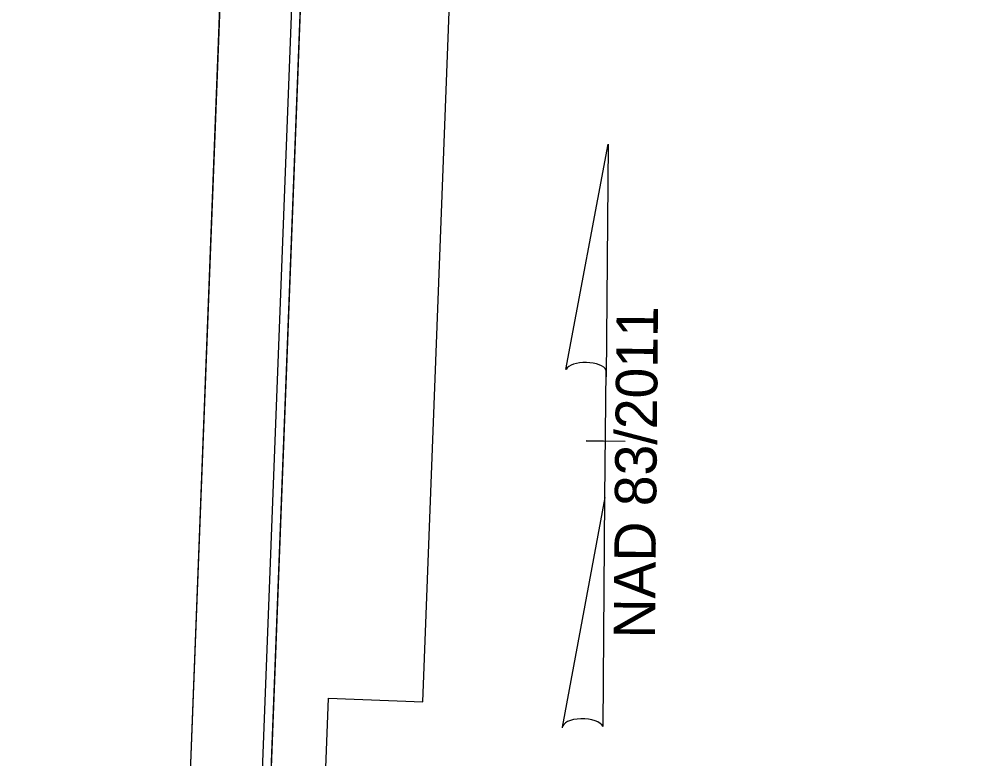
# Model space of a CAD drawing. Extents: x 2097083 to 2098242, y 681809 to 688195.
# Drawn here: x 2097083.2 to 2097350.7, y 687759.7 to 687966 of the extents above; entities that cross this region are included whole.
import ezdxf

# ---------------------------------------------------------------- set-up
doc = ezdxf.new("R2010")
doc.units = 0
for name, color, linetype in [('Prop North Arrow NAD83 for Plan Sheets CELL', 7, 'Continuous'), ('Scratch_Level_6', 7, 'Continuous'), ('Sheet Cutting Line CELL', 7, 'Continuous'), ('Sheet Plan CELL', 7, 'Continuous'), ('Sheet Plot Border Inside CELL', 7, 'Continuous'), ('Sheet Plot Border Outside CELL', 7, 'Continuous')]:
    doc.layers.add(name, color=color, linetype=linetype)

msp = doc.modelspace()

# ---------------------------------------------------------------- linework, layer by layer
at = {"layer": 'Prop North Arrow NAD83 for Plan Sheets CELL'}
for p, q in [((2097235.67, 687868.29), (2097247.39, 687931.13)), ((2097247.46, 687931.13), (2097246.86, 687866.22)), ((2097246.54, 687832.54), (2097246.87, 687868.12)), ((2097246.86, 687866.22), (2097246.87, 687868.05)), ((2097246.08, 687848.3), (2097241.26, 687848.34)), ((2097241.33, 687848.34), (2097252.19, 687848.24)), ((2097246.54, 687832.54), (2097234.61, 687768.48)), ((2097246.02, 687768.64), (2097246.54, 687832.54))]:
    msp.add_line(p, q, dxfattribs=at)
for centre, start_param, end_param in [((2097241.28, 687867.57), 0.216388, 2.908219), ((2097240.36, 687768.2), 0.201328, 3.141593)]:
    msp.add_ellipse(centre, major_axis=(5.74, -0.09), ratio=0.461098, start_param=start_param, end_param=end_param, dxfattribs=at)
at = {"layer": 'Scratch_Level_6'}
msp.add_lwpolyline([(2098163.94, 686705.88), (2097129.59, 686735.95), (2097169.5, 687776.57), (2097195.74, 687775.56), (2097203.4, 687975.46), (2097338.1, 687970.31), (2097342.47, 688084.23), (2098215.52, 688050.75)], close=True, dxfattribs=at)
at = {"layer": 'Sheet Cutting Line CELL'}
msp.add_line((2097147.77, 688194.8), (2097083.25, 686512.54), dxfattribs=at)
at = {"layer": 'Sheet Plan CELL'}
for points in [[(2097169.59, 688176.98), (2097112.1, 686678.04), (2098161.33, 686637.81), (2098218.82, 688136.72)], [(2098161.33, 686637.81), (2097112.13, 686678.02), (2097161.91, 687977.05), (2097311.86, 687971.31), (2097319.54, 688171.2), (2098218.82, 688136.72)]]:
    msp.add_lwpolyline(points, close=True, dxfattribs=at)
at = {"layer": 'Sheet Plot Border Inside CELL'}
msp.add_lwpolyline([(2098157.96, 686484.33), (2098221.79, 688149.1), (2097167.58, 688189.54), (2097103.73, 686524.77)], close=True, dxfattribs=at)
at = {"layer": 'Sheet Plot Border Outside CELL'}
msp.add_lwpolyline([(2098177.45, 686470.58), (2098241.96, 688152.84), (2097147.77, 688194.8), (2097083.25, 686512.54)], close=True, dxfattribs=at)

# ---------------------------------------------------------------- texts
at = {"layer": 'Prop North Arrow NAD83 for Plan Sheets CELL'}
msp.add_text('NAD 83/2011', height=11.5436, rotation=89.4689, dxfattribs=at).set_placement((2097260.47, 687793.2))

doc.saveas('drawing.dxf')
